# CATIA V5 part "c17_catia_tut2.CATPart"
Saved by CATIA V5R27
Part number: Part1
Bounding box of the stored display mesh (mm): x -65 to 65, y -120 to 120, z -37.621 to 37.5
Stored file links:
  E:\_Deepak\2016_Deepak\CATIA\CATIA V5-6R2016_Deepak\Resources\Tutorial Files\Tutorials\c18_catia_v5_6r2016_tut\c18_catia_tut2.CATPart
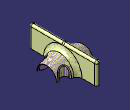
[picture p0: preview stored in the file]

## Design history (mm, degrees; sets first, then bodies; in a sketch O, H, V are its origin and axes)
Body1 (main body)
  Sketch1 on zx-plane, origin (0, 0, 0), H (-1, 0, 0), V (0, 0, 1)
    line L1 (7.5, 37.5) -> (7.5, -37.5)
    line L2 (-7.5, -37.5) -> (-7.5, 37.5)
    line L3 (-7.5, 37.5) -> (7.5, 37.5)
    point P2 (7.5, -37.5)
    distance L1 L2 = 15
    length L1 = 75
    distance H P2 = 37.5
    vertical: L1 V, L2 V
    horizontal: L3 H
    equidistance: L1 L2 O
  Extrude1: Element1 Sketch1, Lim1 120, Lim2 120
  Sketch2 on face of Extrude1 from Sketch1.L2, origin (7.5, 0, 0), H (0, -1, 0), V (0, 0, 1)
    arc A1 centre (0, -37.6505) radius 55 from (55, -37.6505) to (-55, -37.6505) ccw
    point P1 (0, -37.6505)
    axis line L1 (-118.7489, -37.6505) -> (99.6231, -37.6505)
    point P4 (-55, -37.6505)
    point P5 (55, -37.6505)
    radius A1 = 55
    coincidence: P1 V, L1 P4, L1 P5
    horizontal: L1 H
  Plane1: type Offset, RefPlane yz-plane, Offset 65
  Sketch3 on Plane1, origin (65, 0, 0), H (0, 1, 0), V (0, 0, 1)
    arc A1 centre (0, -37.9724) radius 35 from (34.9968, -37.5) to (-34.9968, -37.5) ccw
    point P1 (0, -37.9724)
    axis line L1 (106.4819, -37.5) -> (-95.6002, -37.5)
    reference projected line E1 (-120, -37.5) -> (120, -37.5) from edge of Extrude1
    point P4 (-34.9968, -37.5)
    point P5 (34.9968, -37.5)
    radius A1 = 35
    coincidence: P1 V, L1 E1, L1 P4, L1 P5
    horizontal: L1 H
  Loft1: Sections (Sketch3; Sketch2)
  Symmetry1: ToTransfor Loft1, Reference yz-plane
  Line1: type PtPt, FirstPoint vertex [face of Extrude1 from Sketch1.L2], SecondPoint vertex [face of Extrude1 from Sketch1.L1]
  Fill1: Boundary (edge of Extrude1; edge of Extrude1; edge of Extrude1; Line1)
  Line2: type PtPt, FirstPoint vertex [face of Extrude1 from Sketch1.L1], SecondPoint vertex [face of Extrude1 from Sketch1.L2]
  Fill2: Boundary (edge of Extrude1; edge of Extrude1; edge of Extrude1; Line2)
  Trim1: Trimmed (Loft1; Extrude1)
  Trim2: Trimmed (Symmetry1; Trim1)
  Join1: Elements (Fill1; Trim2; Fill2)
  Sketch4 on xy-plane, origin (0, 0, 0), H (1, 0, 0), V (0, 1, 0)
    circle A1 centre (43, 42) radius 15
    point P1 (43, 42)
    circle A2 centre (43, -42) radius 15
    distance P1 H = 42
    radius A1 = 15
    symmetry: A1 A2 H
  Extrude2: Element1 Sketch4, Lim1 40, Lim2 0, FirstUpto vertex [face of Loft1]
  Trim3: Trimmed (Extrude2; Join1)
  Fillet1: radius 18, on edge [face of Extrude1 from Sketch1.L2 | face of Loft1]; edge [face of Symmetry1 | face of Extrude1 from Sketch1.L1]
  Fillet2: radius 4, on edge [face of Loft1 | face of Extrude2 from Sketch4.A1]
  Fillet3: radius 7.5, on edge [face of Fill1 | face of Extrude1 from Sketch1.L3]; edge [face of Extrude1 from Sketch1.L3 | face of Fill2]; edge [face of Extrude1 from Sketch1.L2 | face of Extrude1 from Sketch1.L3]; edge [face of Extrude1 from Sketch1.L3 | face of Extrude1 from Sketch1.L1]; edge [face of Extrude1 from Sketch1.L2 | face of Fill2]; edge [face of Fill1 | face of Extrude1 from Sketch1.L2]; edge [face of Fill1 | face of Extrude1 from Sketch1.L1]; edge [face of Extrude1 from Sketch1.L1 | face of Fill2]
  Fillet4: radius 4, on edge [face of Extrude2 from Sketch4.A2 | face of Loft1]
  Set1
    ThickSurface1: BotOffset 0, Surface Fillet4, TopOffset 1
